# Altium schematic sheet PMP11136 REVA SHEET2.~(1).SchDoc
size 431 x 279 mm; Date: Not shown in title block; ApprovedBy: Not shown in title block; CheckedBy: Not shown in title block; Author: Not shown in title block; CompanyName: Not shown in title block; Engineer: Not shown in title block; Organization: Not shown in title block; Address1: Not shown in title block; Address2: Not shown in title block; Address3: Not shown in title block; Address4: Not shown in title block; DocumentNumber: 2; Revision: Use project parameter SCH_Rev; SheetNumber: 2; SheetTotal: 3; PageSetup: Record=PageOptions¦CenterHorizontal=True¦CenterVertical=True¦PrintScale=1.00¦XCorrection=1.00¦YCorrection=1.00¦PrintKind=0¦BorderSize=5000000¦LeftOffset=0¦BottomOffset=0¦Orientation=2¦PaperLength=1000¦PaperWidth=1000¦Scale=100¦PaperSource=15¦PrintQuality=600¦MediaType=1¦DitherType=10¦PaperKind=Letter¦PrintScaleMode=1
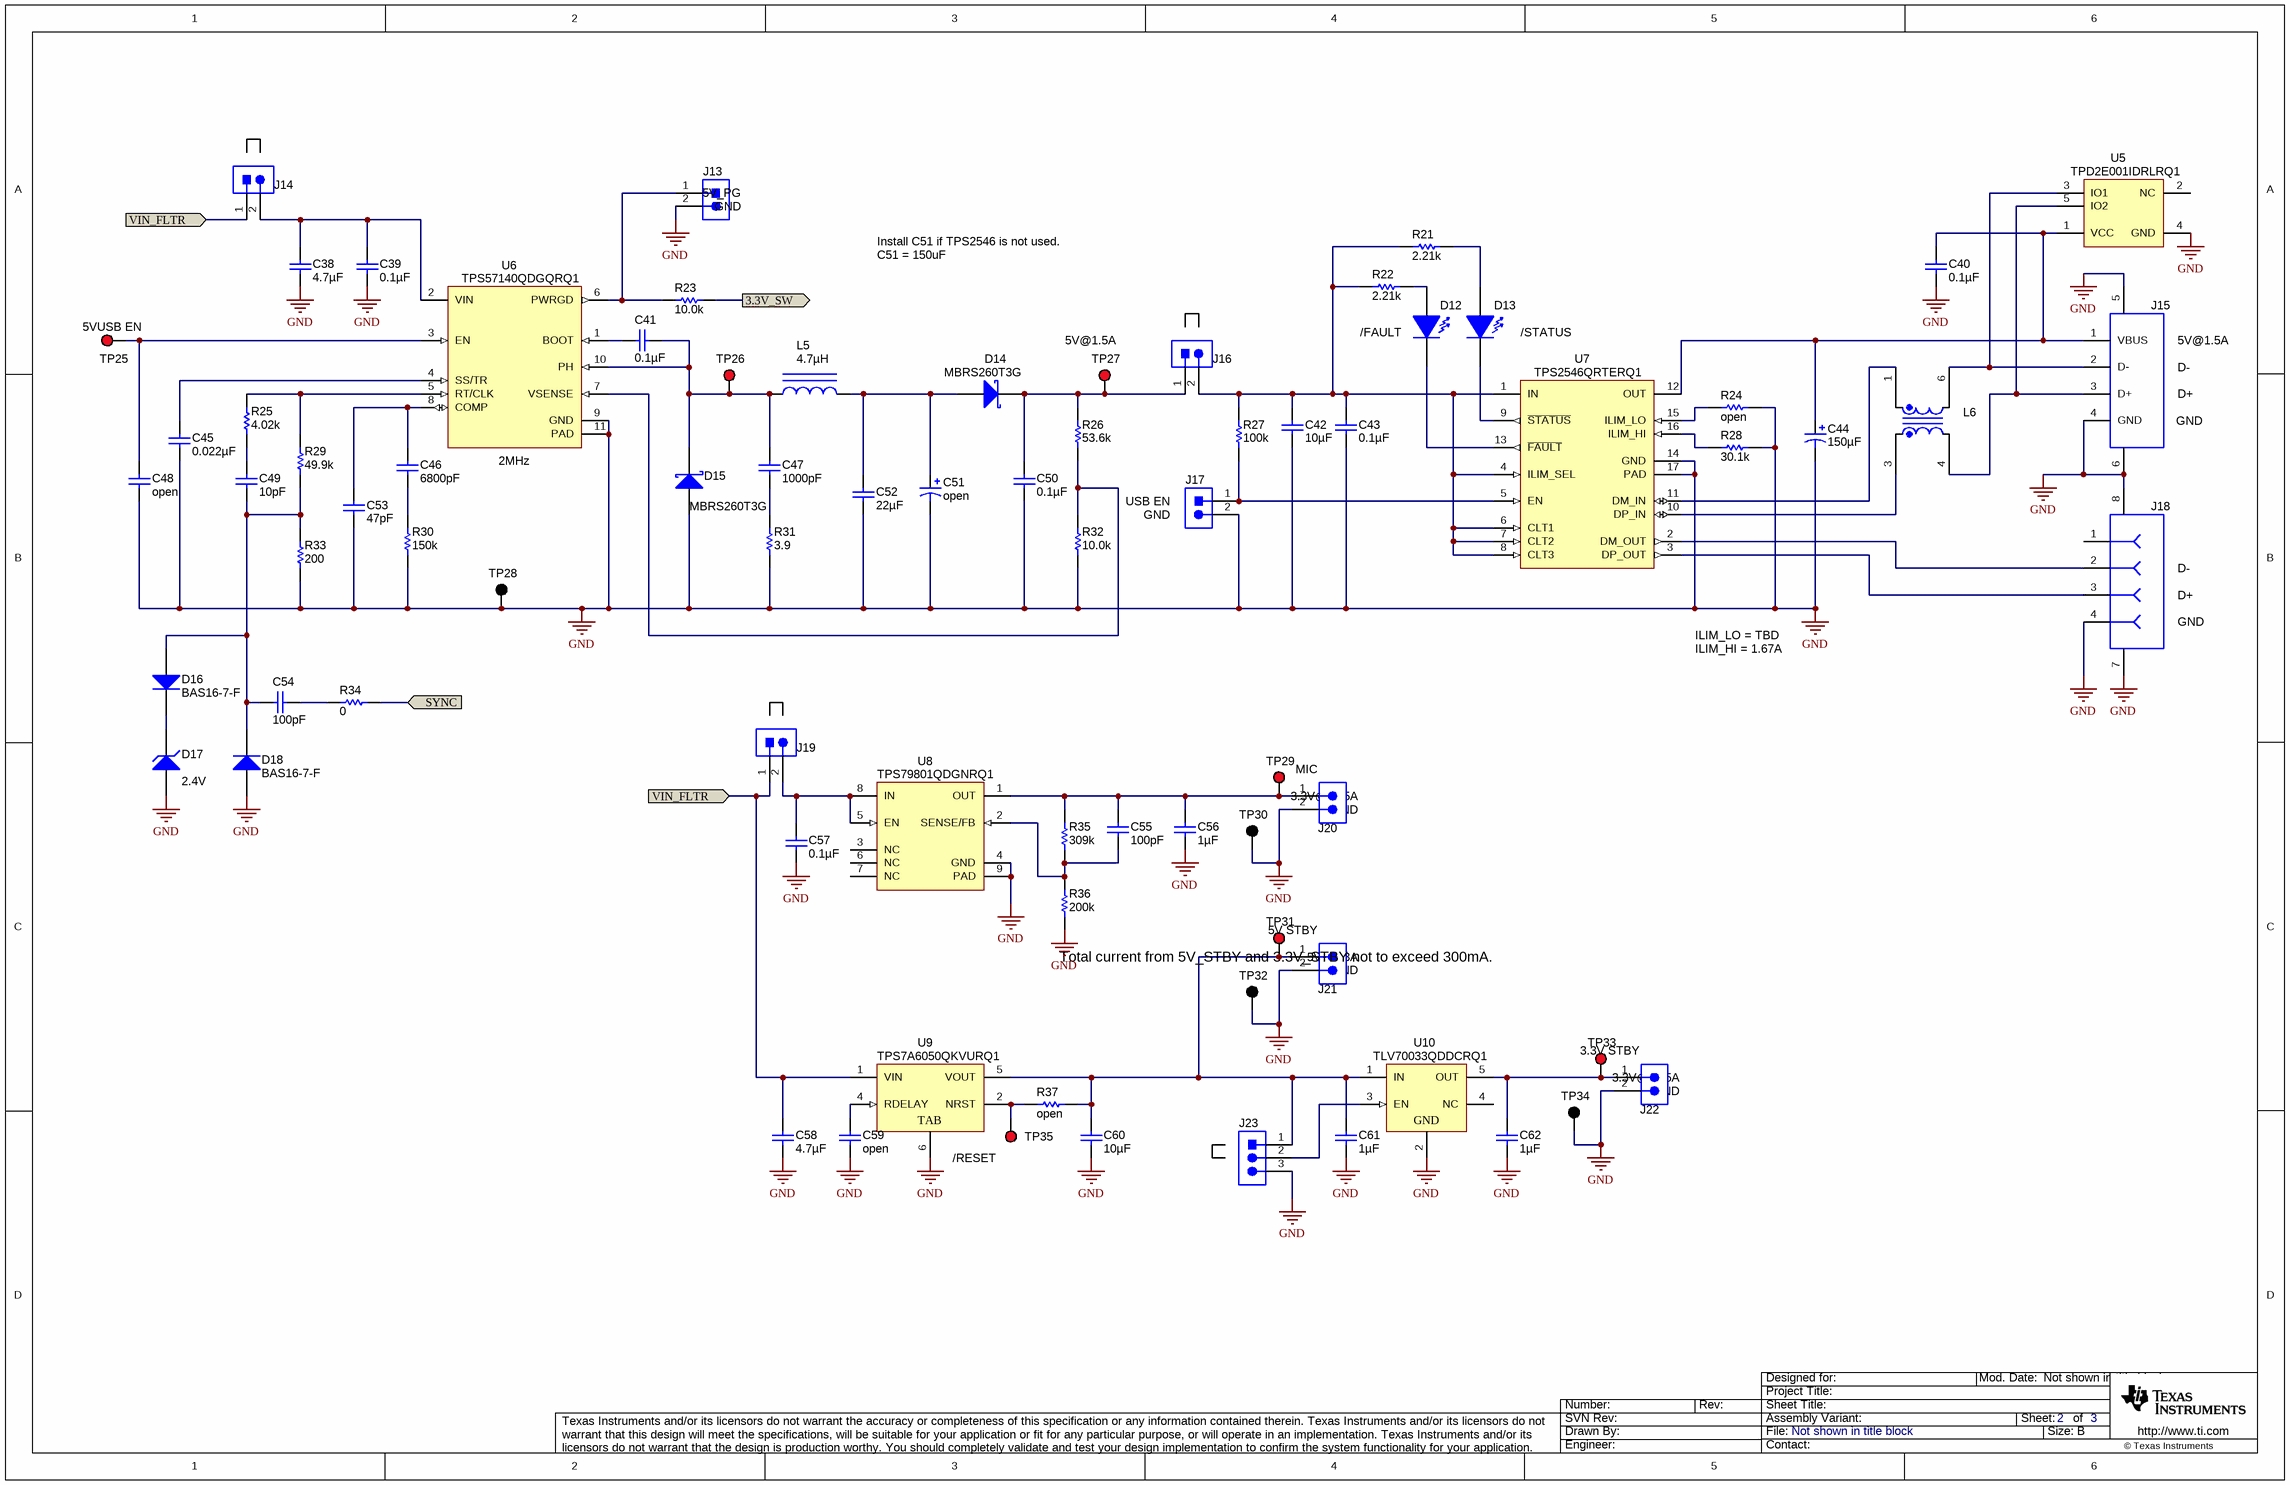
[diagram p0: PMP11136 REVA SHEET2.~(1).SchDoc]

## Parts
C38  ValueDisplayed: 4.7µF  [1210]  (hidden comment: C3225X7R1H475M250AB)
C39  ValueDisplayed: 0.1µF  [0603]  (hidden comment: C1608X7R1H104K)
C40  ValueDisplayed: 0.1µF  [0603]  (hidden comment: C1608X7R1H104K)
C41  ValueDisplayed: 0.1µF  [0603]  (hidden comment: C1608X7R1H104K)
C42  ValueDisplayed: 10µF  [0805]  (hidden comment: GRM21BR71A106KE51L)
C43  ValueDisplayed: 0.1µF  [0603]  (hidden comment: C1608X7R1H104K)
C44  ValueDisplayed: 150µF  [TPB_D4]  (hidden comment: 10TPB150ML)
C45  ValueDisplayed: 0.022µF  [0603]  (hidden comment: C1608X7R1H223K)
C46  ValueDisplayed: 6800pF  [0603]  (hidden comment: C1608C0G1E682J)
C47  ValueDisplayed: 1000pF  [0603]  (hidden comment: C1608C0G2A102J)
C48  ValueDisplayed: open  [0603]
C49  ValueDisplayed: 10pF  [0603]  (hidden comment: C1608C0G1H100D)
C50  ValueDisplayed: 0.1µF  [0603]  (hidden comment: C1608X7R1H104K)
C51  ValueDisplayed: open  [TPB_D4]
C52  ValueDisplayed: 22µF  [1210]  (hidden comment: C3225X7R1A226M230AC)
C53  ValueDisplayed: 47pF  [0603]  (hidden comment: C1608C0G1H470J)
C54  ValueDisplayed: 100pF  [0603]  (hidden comment: C1608C0G1H101J)
C55  ValueDisplayed: 100pF  [0603]  (hidden comment: C1608C0G1H101J)
C56  ValueDisplayed: 1µF  [0603]  (hidden comment: C1608X7R1E105K)
C57  ValueDisplayed: 0.1µF  [0603]  (hidden comment: C1608X7R1H104K)
C58  ValueDisplayed: 4.7µF  [1210]  (hidden comment: C3225X7R1H475M250AB)
C59  ValueDisplayed: open  [0603]
C60  ValueDisplayed: 10µF  [0805]  (hidden comment: GRM21BR71A106KE51L)
C61  ValueDisplayed: 1µF  [0603]  (hidden comment: C1608X7R1E105K)
C62  ValueDisplayed: 1µF  [0603]  (hidden comment: C1608X7R1E105K)
D12  value /FAULT  [LED_LTST-C190]  (hidden comment: LTST-C190GKT)
D13  value /STATUS  [LED_LTST-C190]  (hidden comment: LTST-C190GKT)
D14  MBRS260T3G  [SMB]
D15  MBRS260T3G  [SMB]
D16  BAS16-7-F  [SOT-23]
D17  value 2.4V  [SOD-123]  (hidden comment: MMSZ5221B-7-F)
D18  BAS16-7-F  [SOT-23]
J13  PEC02SAAN  [CONN_PEC02SAAN]  (value not drawn)
J14  PEC02SAAN  [CONN_PEC02SAAN]  (value not drawn)
J15  676430910  [MOLEX_0676430910]  (value not drawn)
J16  PEC02SAAN  [CONN_PEC02SAAN]  (value not drawn)
J17  PEC02SAAN  [CONN_PEC02SAAN]  (value not drawn)
J18  48037-1000  [CONN_USB-A-48037-1000]  (value not drawn)
J19  PEC02SAAN  [CONN_PEC02SAAN]  (value not drawn)
J20  ED555/2DS  [TERM_BLK_ED555-2DS]  (value not drawn)
J21  ED555/2DS  [TERM_BLK_ED555-2DS]  (value not drawn)
J22  ED555/2DS  [TERM_BLK_ED555-2DS]  (value not drawn)
J23  PEC03SAAN  [CONN_PEC03SAAN]  (value not drawn)
L5  ValueDisplayed: 4.7µH  [SDR7045]  (hidden comment: SLF6045T-4R7N2R4-3PF)
L6  985DH-1026  [NT2012]  (value not drawn)
R21  ValueDisplayed: 2.21k  [0603]  (hidden comment: CRCW06032K21FKEA)
R22  ValueDisplayed: 2.21k  [0603]  (hidden comment: CRCW06032K21FKEA)
R23  ValueDisplayed: 10.0k  [0603]  (hidden comment: CRCW060310K0FKEA)
R24  ValueDisplayed: open  [0603]
R25  ValueDisplayed: 4.02k  [0603]  (hidden comment: CRCW06034K02FKEA)
R26  ValueDisplayed: 53.6k  [0603]  (hidden comment: CRCW060353K6FKEA)
R27  ValueDisplayed: 100k  [0603]  (hidden comment: CRCW0603100KFKEA)
R28  ValueDisplayed: 30.1k  [0603]  (hidden comment: CRCW060330K1FKEA)
R29  ValueDisplayed: 49.9k  [0603]  (hidden comment: CRCW060349K9FKEA)
R30  ValueDisplayed: 150k  [0603]  (hidden comment: CRCW0603150KFKEA)
R31  value 3.9  [2010]  (hidden comment: CRCW20103R90JNEF)
R32  ValueDisplayed: 10.0k  [0603]  (hidden comment: CRCW060310K0FKEA)
R33  ValueDisplayed: 200  [0603]  (hidden comment: CRCW0603200RFKEA)
R34  ValueDisplayed: 0  [0603]  (hidden comment: CRCW06030000Z0EA)
R35  ValueDisplayed: 309k  [0603]  (hidden comment: CRCW0603309KFKEA)
R36  ValueDisplayed: 200k  [0603]  (hidden comment: CRCW0603200KFKEA)
R37  ValueDisplayed: open  [0603]
TP25  5000  [Keystone5000]  (value not drawn)
TP26  5000  [Keystone5000]  (value not drawn)
TP27  5000  [Keystone5000]  (value not drawn)
TP28  5001  [Keystone5001]  (value not drawn)
TP29  5000  [Keystone5000]  (value not drawn)
TP30  5001  [Keystone5001]  (value not drawn)
TP31  5000  [Keystone5000]  (value not drawn)
TP32  5001  [Keystone5001]  (value not drawn)
TP33  5000  [Keystone5000]  (value not drawn)
TP34  5001  [Keystone5001]  (value not drawn)
TP35  5000  [Keystone5000]  (value not drawn)
U5  TPD2E001IDRLRQ1  [DRL0005A]
U6  TPS57140QDGQRQ1  [DGQ0010D_N]
U7  TPS2546QRTERQ1  [RTE0016C]
U8  TPS79801QDGNRQ1  [DGN0008B_N]
U9  TPS7A6050QKVURQ1  [KVU0005A_N]
U10  TLV70033QDDCRQ1  [DDC0005A_N]

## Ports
3.3V_SW, SYNC, VIN_FLTR

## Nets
GND: C38.1 C39.2 C40.2 C42.2 C43.2 C44.2(-) C45.2 C48.2 C50.2 C51.2(-) C52.2 C53.2 C56.2 C57.2 C58.1 C59.2 C60.2 C61.2 C62.2 D15.2(A) D17.2(A) D18.1(A) J13.2 J15.4(GND) J15.5(Shield) J15.6(Shield) J17.2 J18.4 J18.7 J18.8 J20.2 J21.2 J22.2 J23.3 R24.1 R28.1 R30.1 R31.1 R32.1 R33.1 R36.1 TP28.1 TP30.1 TP32.1 TP34.1 U5.4(GND) U6.9(GND) U6.11(PAD) U7.14(GND) U7.17(PAD) U8.4(GND) U8.9(PAD) U9.6(TAB) U10.2(GND)
3.3V_SW: R23.1 ; port 3.3V_SW
SYNC: R34.1 ; port SYNC
VIN_FLTR: C58.2 J14.1 J19.1 U9.1(VIN) ; port VIN_FLTR
NetC38_2: C38.2 C39.1 J14.2 U6.2(VIN)
NetC40_1: C40.1 C44.1(+) J15.1(VBUS) U5.1(VCC) U7.12(OUT)
NetC41_1: C41.1 U6.1(BOOT)
NetC41_2: C41.2 C47.1 D15.1(K) L5.1 TP26.1 U6.10(PH)
NetC42_1: C42.1 C43.1 J16.2 R21.2 R22.2 R27.2 U7.1(IN) U7.4(ILIM_SEL) U7.6(CLT1) U7.7(CLT2) U7.8(CLT3)
NetC45_1: C45.1 U6.4(SS/TR)
NetC46_1: C46.1 C53.1 U6.8(COMP)
NetC46_2: C46.2 R30.2
NetC47_2: C47.2 R31.2
NetC48_1: C48.1 TP25.1 U6.3(EN)
NetC49_1: C49.1 R25.2
NetC49_2: C49.2 C54.1 D16.1(A) D18.3(K) R29.1 R33.2
NetC50_1: C50.1 D14.1(K) J16.1 R26.2 TP27.1
NetC51_1: C51.1(+) C52.1 D14.2(A) L5.2
NetC54_2: C54.2 R34.2
NetC55_1: C55.1 C56.1 J20.1 R35.2 TP29.1 U8.1(OUT)
NetC55_2: C55.2 R35.1 R36.2 U8.2(SENSE/FB)
NetC57_1: C57.1 J19.2 U8.5(EN) U8.8(IN)
NetC59_1: C59.1 U9.4(RDELAY)
NetC60_1: C60.1 C61.1 J21.1 J23.1 R37.2 TP31.1 U9.5(VOUT) U10.1(IN)
NetC62_1: C62.1 J22.1 TP33.1 U10.5(OUT)
NetD12_1: D12.1(A) R22.1
NetD12_2: D12.2(K) U7.13(~{FAULT})
NetD13_1: D13.1(A) R21.1
NetD13_2: D13.2(K) U7.9(~{STATUS})
NetD16_3: D16.3(K) D17.1(K)
NetJ13_1: J13.1 R23.2 U6.6(PWRGD)
NetJ15_2: J15.2(D-) L6.6 U5.3(IO1)
NetJ15_3: J15.3(D+) L6.4 U5.5(IO2)
NetJ17_1: J17.1 R27.1 U7.5(EN)
NetJ18_2: J18.2 U7.2(DM_OUT)
NetJ18_3: J18.3 U7.3(DP_OUT)
NetJ23_2: J23.2 U10.3(EN)
NetL6_1: L6.1 U7.11(DM_IN)
NetL6_3: L6.3 U7.10(DP_IN)
NetR24_2: R24.2 U7.15(ILIM_LO)
NetR25_1: R25.1 R29.2 U6.5(RT/CLK)
NetR26_1: R26.1 R32.2 U6.7(VSENSE)
NetR28_2: R28.2 U7.16(ILIM_HI)
NetR37_1: R37.1 TP35.1 U9.2(NRST)

Not connected (* = marked no-connect by the designer): J18 1; U5 2(NC); U8 3(NC) 6(NC) 7(NC); U10 4(NC)

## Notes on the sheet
- (near J13) 5V_PG
- (near J13) GND
- Install C51 if TPS2546 is not used.
  C51 = 150uF
- (near TP25) 5VUSB EN
- (near TP27) 5V@1.5A
- 5V@1.5A
- D-
- D+
- GND
- (near U6) 2MHz
- USB EN
- (near J17) GND
- ILIM_LO = TBD
- ILIM_HI = 1.67A
- (near J20) MIC
- (near J20) 3.3V@0.05A
- (near J20) GND
- (near J21) 5V STBY
- (near J21) 5V@0.3A
- (near J21) GND
- Total current from 5V_STBY and 3.3V_STBY not to exceed 300mA.
- (near J22) 3.3V STBY
- (near J22) 3.3V@0.05A
- (near J22) GND
- /RESET

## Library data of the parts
C38 C58 = C3225X7R1E106M: CAP, CERM, 4.7uF, 50V, +/-20%, X7R, 1210; Manufacturer: TDK; Polarized: N; CompType: Capacitor; U/M: EA; Cap_F: 0.00001; Tolerance_%: 20; ESR_Ohm: 0.0027; Value1: 0.0027 ohm; VDC_V: 50; IRMS_A: 3; TaMin_C: -55; TaMax_C: 125
C39-C41 C43 C50 C57 = C1608X7R1H104K: CAP, CERM, 0.1uF, 50V, +/-10%, X7R, 0603; Manufacturer: TDK; Polarized: N; CompType: Capacitor; U/M: EA; Cap_F: 0.0000001; Tolerance_%: 10; ESR_Ohm: 0.017; Value1: 0.017 ohm; VDC_V: 50; TaMin_C: -55; TaMax_C: 125
C42 C60 = GRM21BR71A106KE51L: CAP, CERM, 10uF, 10V, +/-10%, X7R, 0805; Manufacturer: MuRata; Polarized: N; CompType: Capacitor; U/M: EA; Cap_F: 0.00001; Tolerance_%: 10; ESR_Ohm: 0.003; Value1: 0.003 ohm; TaMin_C: -55; TaMax_C: 125
C44 = 10TPB220M: CAP, 150uF, 10V, +/-20%, 0.04 ohm, SMD; Manufacturer: Panasonic; Polarized: Y; CompType: Capacitor; U/M: EA; Cap_F: 0.00022; Tolerance_%: 20; VDC_V: 10; ESR_Ohm: 0.04; IRMS_A: 3; TaMin_C: -55; TaMax_C: 105; Cap_Case: D
C45 = C1608X7R1H223K: CAP, CERM, 0.022 µF, 50 V, +/- 10%, X7R, 0603; Manufacturer: TDK; Polarized: N; CompType: Capacitor; Value: 0.022uF; U/M: EA; Cap_F: 0.000000022; Tolerance_%: 10; ESR_ohm: 0.0383; Value1: 0.0383 ohm; VDC_V: 50; Value2: 50V; TaMin_C: -55; TaMax_C: 125
C46 = C1608C0G1E682J: CAP, CERM, 6800 pF, 25 V, +/- 5%, C0G/NP0, 0603; Manufacturer: TDK; Polarized: N; CompType: Capacitor; Value: 6800pF; U/M: EA; Cap_F: 0.0000000068; Tolerance_%: 5; Value1: Unknown; VDC_V: 25; Value2: 25V; TaMin_C: -55; TaMax_C: 125
C47 = C1608C0G2A102J: CAP, CERM, 1000 pF, 100 V, +/- 5%, C0G/NP0, 0603; Manufacturer: TDK; Polarized: N; CompType: Capacitor; Value: 1000pF; U/M: EA; Cap_F: 0.000000001; Tolerance_%: 5; ESR_ohm: 0.0589; Value1: 0.0589 ohm; VDC_V: 100; Value2: 100V; TaMin_C: -55; TaMax_C: 125
C48 C59 = C1608C0G1H102J: CAP, CERM, open, 0603; Polarized: N; CompType: Capacitor; U/M: EA; Cap_F: 0.000000001; Tolerance_%: 5; ESR_ohm: 0.0563; TempCo: C0G/NP0; TaMin_C: -55; TaMax_C: 125
C49 = C1608C0G1H100D: CAP, CERM, 10 pF, 50 V, +/- 5%, C0G/NP0, 0603; Manufacturer: TDK; Polarized: N; CompType: Capacitor; Value: 10pF; U/M: EA; Cap_F: 0.00000000001; Tolerance_%: 5; ESR_ohm: 0.3492; Value1: 0.3492 ohm; VDC_V: 50; Value2: 50V; TaMin_C: -55; TaMax_C: 125
C51 = 10TPB220M: CAP, open, SMD; Polarized: Y; CompType: Capacitor; U/M: EA; Cap_F: 0.00022; Tolerance_%: 20; ESR_Ohm: 0.04; IRMS_A: 3; TaMin_C: -55; TaMax_C: 105; Cap_Case: D
C52 = C3225X7R1C226M: CAP, CERM, 22 µF, 16 V, +/- 20%, X7R, 1210; Manufacturer: TDK; Polarized: N; CompType: Capacitor; Value: 22uF; U/M: EA; Cap_F: 0.000022; Tolerance_%: 20; ESR_ohm: 0.002; Value1: 0.002 ohm; VDC_V: 16; Value2: 16V; IRMS_A: 8.11; TaMin_C: -55; TaMax_C: 125
C53 = C1608C0G1H470J: CAP, CERM, 47 pF, 50 V, +/- 5%, C0G/NP0, 0603; Manufacturer: TDK; Polarized: N; CompType: Capacitor; Value: 47pF; U/M: EA; Cap_F: 0.000000000047; Tolerance_%: 5; ESR_ohm: 0.22; Value1: 0.22 ohm; VDC_V: 50; Value2: 50V; TaMin_C: -55; TaMax_C: 125
C54 C55 = C1608C0G1H101J: CAP, CERM, 100 pF, 50 V, +/- 5%, C0G/NP0, 0603; Manufacturer: TDK; Polarized: N; CompType: Capacitor; Value: 100pF; U/M: EA; Cap_F: 0.0000000001; Tolerance_%: 5; ESR_ohm: 0.1679; Value1: 0.1679 ohm; VDC_V: 50; Value2: 50V; TaMin_C: -55; TaMax_C: 125
C56 C61 C62 = C1608X7R1C105K: CAP, CERM, 1uF, 25V, +/-10%, X7R, 0603; Manufacturer: TDK; Polarized: N; CompType: Capacitor; U/M: EA; Cap_F: 0.000001; Tolerance_%: 10; ESR_Ohm: 0.0057; Value1: 0.0057 ohm; VDC_V: 25; TaMin_C: -55; TaMax_C: 125
D12 D13 = LTST-C190GKT: LED, Green, SMD; Manufacturer: Lite-On; Vf_V: 2.1; Value2: 2.1V; Io_A: 0.02; Power_TotalModule: 0.1; Value1: 0.1W; U/M: EA
D14 D15 = MBRS260T3G: Diode, Schottky, 60V, 2A, SMB; Manufacturer: ON Semiconductor; U/M: EA; Vf_V: 0.63; Value2: 0.63V; Io_A: 2; Vr_V: 60; TJmax_C: 125; RJC_CperW: 24
D16 D18 = BAS16-7-F: Diode, Ultrafast, 75V, 0.3A, SOT-23; Manufacturer: Diodes Inc.; U/M: EA; Vf_V: 1.125; Value2: 1.125V; Io_A: 0.3; Vr_V: 75
D17 = MMSZ5221B-7-F: Diode, Zener, 2.4V, 500 mW, SOD-123; Manufacturer: Diodes Inc.; SymbolCreator: a0412235; U/M: EA; Power_W: 0.5; Vz_V: 2.4; Value1: 0.5W; RJA_CperW: 350
J13 J14 J16 J17 J19 = PEC02SAAN: Header, 100mil, 2x1, Tin, TH; Manufacturer: Sullins Connector Solutions; SymbolCreator: a0412235; U/M: EA
J15 = 676430910: Connector, Receptacle, USB Standard, R/A, Top Mount TH; Manufacturer: Molex; SymbolCreator: a0412235; U/M: EA
J18 = 48037-1000: Connector, Plug, USB Type A, R/A, Top Mount SMT; Manufacturer: Molex; SymbolCreator: a0412235; U/M: EA
J20-J22 = ED555/2DS: Terminal Block, 6A, 3.5mm Pitch, 2-Pos, TH; Manufacturer: On-Shore Technology, Inc.; SymbolCreator: a0412235; CompType: Connector; U/M: EA
J23 = PEC03SAAN: Header, 100mil, 3x1, Tin, TH; Manufacturer: Sullins Connector Solutions; SymbolCreator: a0799628; U/M: EA
L5 = SDR7045-2R2M: Inductor, SMT, 2.4A, 26.5 milliohm; Manufacturer: Bourns; Value: 4.7uH; Ind_H: 4.7E-6; Imax_A: 2.4; Material: Ferrite
L6 = 985DH-1023: Coupled inductor, 0.28A, 0.36 ohm, SMD; Manufacturer: Toko; SymbolCreator: a0411947; DCR_ohm: 0.21; Isat: 0.37
R21 R22 = CRCW06032K21FKEA: RES, 2.21 k, 1%, 0.1 W, 0603; Manufacturer: Vishay-Dale; CompType: Resistor; Value: 2.21k; Res_ohm: 2210; Value_Code: 2k21; Tolerance_%: 1; Power_W: 0.1; Value2: 0.1W; VDC_V: 75; TempCo: 100 ppm/C; EIA_Code: E96; U/M: EA
R23 R32 = CRCW060310K0FKEA: RES, 10.0 k, 1%, 0.1 W, 0603; Manufacturer: Vishay-Dale; CompType: Resistor; Value: 10.0k; Res_ohm: 10000; Value_Code: 10k0; Tolerance_%: 1; Power_W: 0.1; Value2: 0.1W; VDC_V: 75; TempCo: 100 ppm/C; EIA_Code: E96; U/M: EA
R24 R37 = CRCW060330K1FKEA: RES, open, 1%, 0.1 W, 0603; CompType: Resistor; Res_ohm: 30100; Tolerance_%: 1; Power_W: 0.1; Value2: 0.1W; TempCo: 100 ppm/C; EIA_Code: E96; U/M: EA
R25 = CRCW06034K02FKEA: RES, 4.02 k, 1%, 0.1 W, 0603; Manufacturer: Vishay-Dale; CompType: Resistor; Value: 4.02k; Res_ohm: 4020; Value_Code: 4k02; Tolerance_%: 1; Power_W: 0.1; Value2: 0.1W; VDC_V: 75; TempCo: 100 ppm/C; EIA_Code: E96; U/M: EA
R26 = CRCW060353K6FKEA: RES, 53.6 k, 1%, 0.1 W, 0603; Manufacturer: Vishay-Dale; CompType: Resistor; Value: 53.6k; Res_ohm: 53600; Value_Code: 53k6; Tolerance_%: 1; Power_W: 0.1; Value2: 0.1W; VDC_V: 75; TempCo: 100 ppm/C; EIA_Code: E96; U/M: EA
R27 = CRCW0603100KFKEA: RES, 100 k, 1%, 0.1 W, 0603; Manufacturer: Vishay-Dale; CompType: Resistor; Value: 100k; Res_ohm: 100000; Tolerance_%: 1; Power_W: 0.1; Value2: 0.1W; VDC_V: 75; TempCo: 100 ppm/C; EIA_Code: E96; U/M: EA
R28 = CRCW060330K1FKEA: RES, 30.1 k, 1%, 0.1 W, 0603; Manufacturer: Vishay-Dale; CompType: Resistor; Value: 30.1k; Res_ohm: 30100; Value_Code: 30k1; Tolerance_%: 1; Power_W: 0.1; Value2: 0.1W; VDC_V: 75; TempCo: 100 ppm/C; EIA_Code: E96; U/M: EA
R29 = CRCW060349K9FKEA: RES, 49.9 k, 1%, 0.1 W, 0603; Manufacturer: Vishay-Dale; CompType: Resistor; Value: 49.9k; Res_ohm: 49900; Value_Code: 49k9; Tolerance_%: 1; Power_W: 0.1; Value2: 0.1W; VDC_V: 75; TempCo: 100 ppm/C; EIA_Code: E96; U/M: EA
R30 = CRCW0603150KFKEA: RES, 150 k, 1%, 0.1 W, 0603; Manufacturer: Vishay-Dale; CompType: Resistor; Value: 150k; Res_ohm: 150000; Tolerance_%: 1; Power_W: 0.1; Value2: 0.1W; VDC_V: 75; TempCo: 100 ppm/C; EIA_Code: E96; U/M: EA
R31 = CRCW20102R70JNEF: RES, 3.9 ohm, 5%, 0.75W, 2010; Manufacturer: Vishay-Dale; CompType: Resistor; Value_Code: 3R90; Tolerance_%: 5; Power_W: 0.75; VDC_V: 400; TempCo: 200 ppm/C; EIA_Code: E24; U/M: EA
R33 = CRCW0603200RFKEA: RES, 200, 1%, 0.1 W, 0603; Manufacturer: Vishay-Dale; CompType: Resistor; Value: 200; Value_Code: 200R; Tolerance_%: 1; Power_W: 0.1; Value2: 0.1W; VDC_V: 75; TempCo: 100 ppm/C; EIA_Code: E96; U/M: EA
R34 = CRCW06030000Z0EA: RES, 0, 5%, 0.1 W, 0603; Manufacturer: Vishay-Dale; CompType: Resistor; Value: 0; Value_Code: 0000; Tolerance_%: 5; Power_W: 0.1; Value2: 0.1W; VDC_V: 75; TempCo: 200 ppm/C; EIA_Code: E24; U/M: EA
R35 = CRCW0603309KFKEA: RES, 309 k, 1%, 0.1 W, 0603; Manufacturer: Vishay-Dale; CompType: Resistor; Value: 309k; Res_ohm: 309000; Tolerance_%: 1; Power_W: 0.1; Value2: 0.1W; VDC_V: 75; TempCo: 100 ppm/C; EIA_Code: E96; U/M: EA
R36 = CRCW0603200KFKEA: RES, 200 k, 1%, 0.1 W, 0603; Manufacturer: Vishay-Dale; CompType: Resistor; Value: 200k; Res_ohm: 200000; Tolerance_%: 1; Power_W: 0.1; Value2: 0.1W; VDC_V: 75; TempCo: 100 ppm/C; EIA_Code: E96; U/M: EA
TP25-TP27 TP29 TP31 TP33 TP35 = 5000: Test Point, TH, Miniature, Red; Manufacturer: Keystone; CompType: Test Point Loop; U/M: EA
TP28 TP30 TP32 TP34 = 5001: Test Point, TH, Miniature, Black; Manufacturer: Keystone; CompType: Test Point Loop; U/M: EA
U5 = TPD2E001IDRLRQ1: Automotive Catalog Low-Capacitance + / - 15 kV ESD-Protection Array for High-Speed Data Inter, 2 Channels, -40 to +85 degC, 5-pin SOT (DRL), Green (RoHS & no Sb/Br); Manufacturer: Texas Instruments; Alternate Manufacturer: None; Alternate PartNumber: Equivalent; Breakdown Voltage(Min)(V): 11; IEC 61000-4-2 Air-Gap(+/- kV): 15; IEC 61000-4-2 Contact(+/- kV): 8; IO Capacitance(Typ)(pF): 1.5; IO Leakage Current(nA): 1; SubFamily: ESD Solution; USB High Speed: TRUE
U6 = TPS57140QDGQRQ1: 1.5-A 42-V STEP-DOWN SWIFT(TM) DC-DC CONVERTER WITH Eco-mode(TM) CONTROL, DGQ0010D; Alternate Manufacturer: None; Manufacturer: Texas Instruments; SymbolCreator: a0799628; CompType: IC; U/M: EA
U7 = TPS2546RTE: USB Charging Port Controller and Power Switch with Load Detection, RTE0016C; Alternate Manufacturer: None; Manufacturer: Texas Instruments; SymbolCreator: a0411947; CompType: IC; U/M: EA
U8 = TPS79801QDGNRQ1: 50 mA, 3 V TO 50 V, MICROPOWER, LOW-DROPOUT LINEAR REGULATOR, DGN0008B; Alternate Manufacturer: None; Manufacturer: Texas Instruments; SymbolCreator: a0411947; CompType: IC; U/M: EA
U9 = TPS7A6050QKVURQ1: Single Output Automotive LDO, 300 mA, Fixed 5 V Output, 4 to 40 V Input, 5-pin PFM (KVU), -40 to 125 degC, Green (RoHS & no Sb/Br); Manufacturer: Texas Instruments; Alternate Manufacturer: None; Alternate PartNumber: Equivalent; Accuracy(%): 2; Fixed Output Options(V): 5; Iout(Max)(A): 0.3; Iq(Typ)(mA): 0.02; SubFamily: Single Channel LDO; Vdo(Typ)(mV): 300; Vin(Max)(V): 40; Vin(Min)(V): 4
U10 = TLV70033QDDCRQ1: Single Output Automotive LDO, 200 mA, Fixed 3.3 V Output, 2 to 5.5 V Input, with Low IQ, 5-pin SOT (DDC), -40 to 125 degC, Green (RoHS & no Sb/Br); Manufacturer: Texas Instruments; Alternate Manufacturer: None; Alternate PartNumber: Equivalent; Accuracy(%): 2; Fixed Output Options(V): 3.3; Iout(Max)(A): 0.2; Iq(Typ)(mA): 0.03; SubFamily: Single Channel LDO; Vdo(Typ)(mV): 175; Vin(Max)(V): 5.5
